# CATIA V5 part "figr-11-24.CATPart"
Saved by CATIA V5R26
Part number: Part1
Bounding box of the stored display mesh (mm): x -89.703 to 75.958, y -127.286 to 108.862, z -26.487 to 19.815
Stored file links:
  D:\_Deepak\CATIA\CATIA V5-6R2016_Deepak\Resources\Part files\Partfiles\c11_catia_v5_6r2016_prt\figr-11-24.CATPart
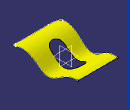
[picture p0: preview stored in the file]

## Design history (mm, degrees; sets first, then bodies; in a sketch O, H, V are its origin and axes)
Set1
  Extrude1: Element1 Sketch3, Lim1 86, Lim2 94, Direction yz-plane
  Sketch1 on xy-plane, origin (0, 0, 0), H (1, 0, 0), V (0, 1, 0)
    line L1 (64.3059, 108.8616) -> (75.9293, -106.0218)
    arc A1 centre (55.7837, -107.1115) radius 20.175 from (75.9293, -106.0218) to (55.7837, -127.2865) cw
    line L2 (55.7837, -127.2865) -> (-64.7868, -127.2865)
    arc A2 centre (-64.7868, -102.3613) radius 24.9252 from (-64.7868, -127.2865) to (-89.6873, -101.2501) cw
    line L3 (-89.6873, -101.2501) -> (-80.3115, 108.8616)
    line L4 (-80.3115, 108.8616) -> (64.3059, 108.8616)
    tangency: A1 L1, A2 L2, A2 L3, A1 L2
    horizontal: L2 H, L4 H
  Extrude2: Element1 Sketch1, Lim1 86, Lim2 94, Direction xy-plane
  Split1: ToCut Extrude1, Cutting Extrude2
  Sketch2 on xy-plane, origin (0, 0, 0), H (1, 0, 0), V (0, 1, 0)
    construction line L1 (-11.3849, 28.4134) -> (-11.3849, -36.9379)
    line L2 (12.8382, 28.4134) -> (12.8382, -36.9379)
    line L3 (-35.608, -36.9379) -> (-35.608, 28.4134)
    arc A1 centre (-11.3849, -36.9379) radius 24.2231 from (12.8382, -36.9379) to (-35.608, -36.9379) cw
    arc A2 centre (-11.3849, 28.4134) radius 24.2231 from (-35.608, 28.4134) to (12.8382, 28.4134) cw
    vertical: L1 V
    tangency: A1 L2, A2 L2, A1 L3, A2 L3
    parallelism: L1 L2
  Extrude3: Element1 Sketch2, Lim1 86, Lim2 94, Direction xy-plane
  Split2: ToCut Split1, Cutting Extrude3
  Boundary1: Boundary edge of Split2, Support Split2
Body1 (main body)
  Sketch3 on yz-plane, origin (0, 0, 0), H (0, 1, 0), V (0, 0, 1)
    spline S1 through (-130.9721, 0) (-85.5087, 19.8151) (-38.0512, 0) (0, -25.6483) (60.0541, -1.7202) (134.7951, -4.3868)
    point P1 (-130.9721, 0)
    point P2 (-38.0512, 0)
    point P3 (0, -25.6483)
    coincidence: P1 H, P2 H, P3 V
